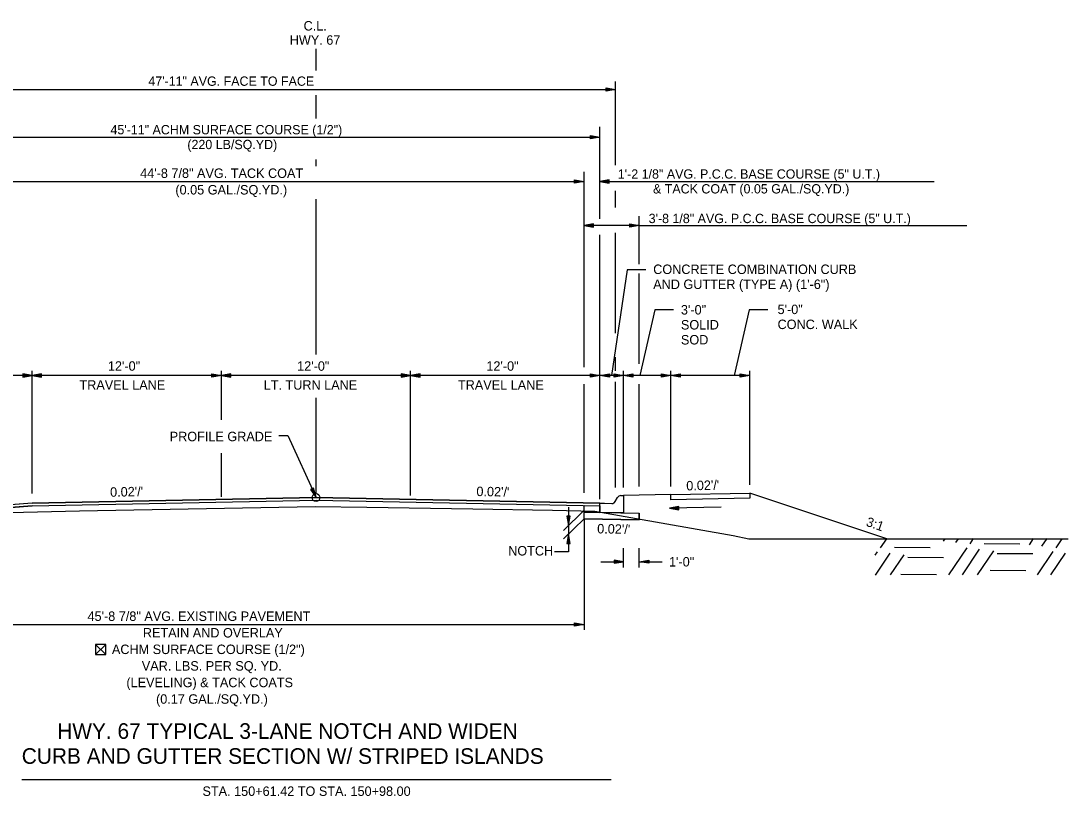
# Model space of a CAD drawing. Extents: x 1001270 to 1003428, y 1840152 to 1842912.
# Drawn here: x 1001595.7 to 1001662.1, y 1841962.8 to 1842011.9 of the extents above; entities that cross this region are included whole.
import ezdxf

# ---------------------------------------------------------------- set-up
doc = ezdxf.new("R2010")
doc.units = 0
for name, color, linetype in [('10', 7, 'Continuous'), ('19', 7, 'Continuous'), ('20', 7, 'Continuous'), ('8', 7, 'Continuous')]:
    doc.layers.add(name, color=color, linetype=linetype)

# ---------------------------------------------------------------- blocks, each defined once
blk = doc.blocks.new('TM')
at = {"layer": '8'}
for p, q in [((-120.309, 21.181), (-119.787, -20.829)), ((0, 0), (-120.309, 21.181)), ((-31.382, 2.945), (-120.176, 10.512)), ((-119.787, -20.829), (0, 0)), ((-119.911, -10.826), (-31.307, -3.057))]:
    blk.add_line(p, q, dxfattribs=at)

msp = doc.modelspace()

# ---------------------------------------------------------------- linework, layer by layer
at = {"layer": '10'}
for p, q in [((1001600.472, 1841972.41), (1001601.114, 1841971.769)), ((1001601.114, 1841972.41), (1001600.472, 1841971.769)), ((1001600.854, 1841971.769), (1001600.865, 1841971.769))]:
    msp.add_line(p, q, dxfattribs=at)
msp.add_lwpolyline([(1001600.865, 1841971.769), (1001601.114, 1841971.769), (1001601.114, 1841972.41), (1001600.472, 1841972.41), (1001600.472, 1841971.769), (1001600.854, 1841971.769)], dxfattribs=at)
at = {"layer": '19'}
for p, q in [((1001614.45, 1842008.782), (1001614.45, 1842010.174)), ((1001585.161, 1842007.592), (1001633.451, 1842007.592)), ((1001632.851, 1842007.487), (1001632.851, 1842007.697)), ((1001632.851, 1842007.697), (1001633.451, 1842007.592)), ((1001632.851, 1842007.642), (1001633.291, 1842007.607)), ((1001633.451, 1842007.592), (1001632.851, 1842007.487)), ((1001633.291, 1842007.577), (1001632.851, 1842007.537)), ((1001633.451, 1842002.779), (1001633.451, 1842008.094)), ((1001614.45, 1842005.749), (1001614.45, 1842007.222)), ((1001632.45, 1841999.391), (1001632.45, 1842005.216)), ((1001586.132, 1842004.564), (1001632.45, 1842004.564)), ((1001631.851, 1842004.459), (1001631.851, 1842004.669)), ((1001631.851, 1842004.669), (1001632.451, 1842004.564)), ((1001631.851, 1842004.614), (1001632.291, 1842004.579)), ((1001632.451, 1842004.564), (1001631.851, 1842004.459)), ((1001632.291, 1842004.549), (1001631.851, 1842004.509)), ((1001614.45, 1842002.732), (1001614.45, 1842003.158)), ((1001631.447, 1841989.976), (1001631.447, 1842002.356)), ((1001586.132, 1842001.756), (1001631.447, 1842001.756)), ((1001630.847, 1842001.651), (1001630.847, 1842001.861)), ((1001630.847, 1842001.861), (1001631.447, 1842001.756)), ((1001630.847, 1842001.806), (1001631.287, 1842001.771)), ((1001631.447, 1842001.756), (1001630.847, 1842001.651)), ((1001631.287, 1842001.741), (1001630.847, 1842001.701)), ((1001633.049, 1842001.861), (1001632.449, 1842001.756)), ((1001632.449, 1842001.756), (1001633.049, 1842001.651)), ((1001632.451, 1842001.756), (1001653.64, 1842001.756)), ((1001633.049, 1842001.806), (1001632.609, 1842001.771)), ((1001632.609, 1842001.741), (1001633.049, 1842001.701)), ((1001633.049, 1842001.651), (1001633.049, 1842001.861)), ((1001633.451, 1842000.11), (1001633.451, 1842001.153)), ((1001614.45, 1841990.776), (1001614.45, 1842000.637)), ((1001634.95, 1841996.51), (1001634.95, 1841999.556)), ((1001632.047, 1841999.061), (1001631.447, 1841998.956)), ((1001634.95, 1841998.956), (1001631.447, 1841998.956)), ((1001631.447, 1841998.956), (1001632.047, 1841998.851)), ((1001632.047, 1841999.006), (1001631.607, 1841998.971)), ((1001631.607, 1841998.941), (1001632.047, 1841998.901)), ((1001632.047, 1841998.851), (1001632.047, 1841999.061)), ((1001634.35, 1841998.851), (1001634.35, 1841999.061)), ((1001634.35, 1841999.061), (1001634.95, 1841998.956)), ((1001634.35, 1841999.006), (1001634.79, 1841998.971)), ((1001634.95, 1841998.956), (1001634.35, 1841998.851)), ((1001634.79, 1841998.941), (1001634.35, 1841998.901)), ((1001634.95, 1841998.956), (1001655.726, 1841998.956)), ((1001632.45, 1841981.606), (1001632.45, 1841998.367)), ((1001633.451, 1841992.137), (1001633.451, 1841998.498)), ((1001634.181, 1841996.147), (1001633.193, 1841989.455)), ((1001635.36, 1841996.147), (1001634.181, 1841996.147)), ((1001634.95, 1841990.196), (1001634.95, 1841995.93)), ((1001635.945, 1841993.612), (1001634.988, 1841989.455)), ((1001637.124, 1841993.612), (1001635.945, 1841993.612)), ((1001641.927, 1841993.612), (1001640.971, 1841989.455)), ((1001643.106, 1841993.612), (1001641.927, 1841993.612)), ((1001633.451, 1841989.747), (1001633.451, 1841990.615)), ((1001596.45, 1841981.966), (1001596.45, 1841989.755)), ((1001608.45, 1841986.642), (1001608.45, 1841989.755)), ((1001620.45, 1841981.846), (1001620.45, 1841989.755)), ((1001632.45, 1841981.606), (1001632.45, 1841989.755)), ((1001633.95, 1841982.356), (1001633.95, 1841989.755)), ((1001636.95, 1841982.416), (1001636.95, 1841989.755)), ((1001641.95, 1841982.516), (1001641.95, 1841989.755)), ((1001596.45, 1841989.455), (1001586.132, 1841989.455)), ((1001595.85, 1841989.56), (1001595.85, 1841989.35)), ((1001596.45, 1841989.455), (1001595.85, 1841989.56)), ((1001596.29, 1841989.47), (1001595.85, 1841989.505)), ((1001595.85, 1841989.35), (1001596.45, 1841989.455)), ((1001595.85, 1841989.4), (1001596.29, 1841989.44)), ((1001597.05, 1841989.56), (1001596.45, 1841989.455)), ((1001608.45, 1841989.455), (1001596.45, 1841989.455)), ((1001596.45, 1841989.455), (1001597.05, 1841989.35)), ((1001597.05, 1841989.505), (1001596.61, 1841989.47)), ((1001596.61, 1841989.44), (1001597.05, 1841989.4)), ((1001597.05, 1841989.35), (1001597.05, 1841989.56)), ((1001607.85, 1841989.35), (1001607.85, 1841989.56)), ((1001607.85, 1841989.56), (1001608.45, 1841989.455)), ((1001607.85, 1841989.505), (1001608.29, 1841989.47)), ((1001608.45, 1841989.455), (1001607.85, 1841989.35)), ((1001608.29, 1841989.44), (1001607.85, 1841989.4)), ((1001609.05, 1841989.56), (1001608.45, 1841989.455)), ((1001620.45, 1841989.455), (1001608.45, 1841989.455)), ((1001608.45, 1841989.455), (1001609.05, 1841989.35)), ((1001609.05, 1841989.505), (1001608.61, 1841989.47)), ((1001608.61, 1841989.44), (1001609.05, 1841989.4)), ((1001609.05, 1841989.35), (1001609.05, 1841989.56)), ((1001619.85, 1841989.56), (1001619.85, 1841989.35)), ((1001620.45, 1841989.455), (1001619.85, 1841989.56)), ((1001620.29, 1841989.47), (1001619.85, 1841989.505)), ((1001619.85, 1841989.35), (1001620.45, 1841989.455)), ((1001619.85, 1841989.4), (1001620.29, 1841989.44)), ((1001621.05, 1841989.56), (1001620.45, 1841989.455)), ((1001632.45, 1841989.455), (1001620.45, 1841989.455)), ((1001620.45, 1841989.455), (1001621.05, 1841989.35)), ((1001621.05, 1841989.505), (1001620.61, 1841989.47)), ((1001620.61, 1841989.44), (1001621.05, 1841989.4)), ((1001621.05, 1841989.35), (1001621.05, 1841989.56)), ((1001631.85, 1841989.35), (1001631.85, 1841989.56)), ((1001631.85, 1841989.56), (1001632.45, 1841989.455)), ((1001631.85, 1841989.505), (1001632.29, 1841989.47)), ((1001632.45, 1841989.455), (1001631.85, 1841989.35)), ((1001632.29, 1841989.44), (1001631.85, 1841989.4)), ((1001632.45, 1841989.455), (1001633.05, 1841989.56)), ((1001641.95, 1841989.455), (1001632.45, 1841989.455)), ((1001633.05, 1841989.35), (1001632.45, 1841989.455)), ((1001632.61, 1841989.47), (1001633.05, 1841989.505)), ((1001633.05, 1841989.4), (1001632.61, 1841989.44)), ((1001633.05, 1841989.56), (1001633.05, 1841989.35)), ((1001633.35, 1841989.35), (1001633.35, 1841989.56)), ((1001633.35, 1841989.56), (1001633.95, 1841989.455)), ((1001633.35, 1841989.505), (1001633.79, 1841989.47)), ((1001633.95, 1841989.455), (1001633.35, 1841989.35)), ((1001633.79, 1841989.44), (1001633.35, 1841989.4)), ((1001633.451, 1841982.347), (1001633.451, 1841989.062)), ((1001633.95, 1841989.455), (1001634.55, 1841989.56)), ((1001634.55, 1841989.35), (1001633.95, 1841989.455)), ((1001634.11, 1841989.47), (1001634.55, 1841989.505)), ((1001634.55, 1841989.4), (1001634.11, 1841989.44)), ((1001634.55, 1841989.56), (1001634.55, 1841989.35)), ((1001634.95, 1841982.417), (1001634.95, 1841988.911)), ((1001636.35, 1841989.35), (1001636.35, 1841989.56)), ((1001636.35, 1841989.56), (1001636.95, 1841989.455)), ((1001636.35, 1841989.505), (1001636.79, 1841989.47)), ((1001636.95, 1841989.455), (1001636.35, 1841989.35)), ((1001636.79, 1841989.44), (1001636.35, 1841989.4)), ((1001636.95, 1841989.455), (1001637.55, 1841989.56)), ((1001637.55, 1841989.35), (1001636.95, 1841989.455)), ((1001637.11, 1841989.47), (1001637.55, 1841989.505)), ((1001637.55, 1841989.4), (1001637.11, 1841989.44)), ((1001637.55, 1841989.56), (1001637.55, 1841989.35)), ((1001641.35, 1841989.35), (1001641.35, 1841989.56)), ((1001641.35, 1841989.56), (1001641.95, 1841989.455)), ((1001641.35, 1841989.505), (1001641.79, 1841989.47)), ((1001641.95, 1841989.455), (1001641.35, 1841989.35)), ((1001641.79, 1841989.44), (1001641.35, 1841989.4)), ((1001631.447, 1841982.025), (1001631.447, 1841988.895)), ((1001614.45, 1841981.966), (1001614.45, 1841988.039)), ((1001608.45, 1841981.766), (1001608.45, 1841984.521)), ((1001614.296, 1841982.305), (1001614.106, 1841982.218)), ((1001614.393, 1841981.865), (1001614.249, 1841982.279)), ((1001614.45, 1841981.716), (1001614.296, 1841982.305)), ((1001596.45, 1841981.356), (1001614.45, 1841981.716)), ((1001614.106, 1841982.218), (1001614.45, 1841981.716)), ((1001614.149, 1841982.234), (1001614.369, 1841981.856)), ((1001614.45, 1841981.716), (1001632.45, 1841981.356)), ((1001633.421, 1841981.466), (1001633.567, 1841981.717)), ((1001633.783, 1841981.841), (1001633.95, 1841981.841)), ((1001636.951, 1841981.902), (1001633.95, 1841981.841)), ((1001633.95, 1841981.841), (1001633.95, 1841981.508)), ((1001636.951, 1841981.902), (1001641.95, 1841982.001)), ((1001636.951, 1841981.568), (1001636.951, 1841981.902)), ((1001636.951, 1841981.902), (1001636.951, 1841981.902)), ((1001641.95, 1841981.668), (1001636.951, 1841981.568)), ((1001650.64, 1841979.104), (1001641.95, 1841982.001)), ((1001641.95, 1841982.001), (1001641.95, 1841981.668)), ((1001596.45, 1841981.356), (1001586.132, 1841980.557)), ((1001596.45, 1841981.19), (1001586.132, 1841980.391)), ((1001596.45, 1841981.19), (1001614.45, 1841981.55)), ((1001614.45, 1841981.55), (1001632.45, 1841981.19)), ((1001631.447, 1841980.376), (1001631.447, 1841981.21)), ((1001631.447, 1841981.21), (1001632.45, 1841981.19)), ((1001631.447, 1841980.793), (1001631.447, 1841981.21)), ((1001631.447, 1841981.21), (1001631.447, 1841981.21)), ((1001632.45, 1841981.356), (1001632.734, 1841981.351)), ((1001632.45, 1841981.19), (1001632.45, 1841980.773)), ((1001632.734, 1841981.351), (1001632.734, 1841981.35)), ((1001632.734, 1841981.35), (1001632.734, 1841981.351)), ((1001632.734, 1841981.351), (1001633.2, 1841981.341)), ((1001633.95, 1841981.508), (1001633.95, 1841981.326)), ((1001633.95, 1841981.326), (1001633.95, 1841980.746)), ((1001631.447, 1841980.907), (1001630.147, 1841979.634)), ((1001631.447, 1841980.376), (1001630.147, 1841979.104)), ((1001630.561, 1841980.538), (1001630.351, 1841980.538)), ((1001630.351, 1841980.538), (1001630.456, 1841979.938)), ((1001630.406, 1841980.538), (1001630.441, 1841980.098)), ((1001630.456, 1841979.938), (1001630.561, 1841980.538)), ((1001630.471, 1841980.098), (1001630.511, 1841980.538)), ((1001631.447, 1841980.793), (1001632.45, 1841980.773)), ((1001632.45, 1841980.773), (1001631.447, 1841980.793)), ((1001631.447, 1841980.793), (1001634.95, 1841980.726)), ((1001631.447, 1841980.376), (1001631.447, 1841980.793)), ((1001631.447, 1841980.793), (1001631.447, 1841980.793)), ((1001631.447, 1841980.376), (1001631.447, 1841973.323)), ((1001631.447, 1841980.376), (1001634.95, 1841980.306)), ((1001634.95, 1841980.306), (1001631.447, 1841980.376)), ((1001633.95, 1841980.746), (1001632.45, 1841980.776)), ((1001633.95, 1841980.746), (1001634.95, 1841980.726)), ((1001634.95, 1841980.306), (1001634.95, 1841980.726)), ((1001634.95, 1841980.726), (1001634.95, 1841980.306)), ((1001630.456, 1841979.407), (1001630.351, 1841978.807)), ((1001630.441, 1841979.247), (1001630.401, 1841978.807)), ((1001630.561, 1841978.807), (1001630.456, 1841979.407)), ((1001630.506, 1841978.807), (1001630.471, 1841979.247)), ((1001650.249, 1841978.521), (1001650.64, 1841979.104)), ((1001654.234, 1841978.956), (1001654.34, 1841979.106)), ((1001655.029, 1841978.864), (1001655.195, 1841979.108)), ((1001655.924, 1841978.772), (1001656.15, 1841979.11)), ((1001659.688, 1841978.716), (1001659.95, 1841979.111)), ((1001660.483, 1841978.624), (1001660.815, 1841979.113)), ((1001661.378, 1841978.532), (1001661.759, 1841979.106)), ((1001630.351, 1841978.807), (1001630.561, 1841978.807)), ((1001633.95, 1841977.273), (1001633.95, 1841978.511)), ((1001634.95, 1841977.273), (1001634.95, 1841978.511)), ((1001651.137, 1841978.561), (1001653.397, 1841978.539)), ((1001654.586, 1841976.808), (1001655.738, 1841978.53)), ((1001655.441, 1841976.811), (1001656.533, 1841978.438)), ((1001656.396, 1841976.813), (1001657.428, 1841978.346)), ((1001656.812, 1841978.801), (1001659.073, 1841978.79)), ((1001660.196, 1841976.814), (1001661.193, 1841978.29)), ((1001630.456, 1841978.279), (1001629.582, 1841978.279)), ((1001632.501, 1841977.651), (1001633.95, 1841977.651)), ((1001632.501, 1841977.651), (1001633.95, 1841977.651)), ((1001633.35, 1841977.756), (1001633.35, 1841977.546)), ((1001633.95, 1841977.651), (1001633.35, 1841977.756)), ((1001633.35, 1841977.756), (1001633.35, 1841977.546)), ((1001633.95, 1841977.651), (1001633.35, 1841977.756)), ((1001633.79, 1841977.666), (1001633.35, 1841977.701)), ((1001633.79, 1841977.666), (1001633.35, 1841977.701)), ((1001633.35, 1841977.546), (1001633.95, 1841977.651)), ((1001633.35, 1841977.546), (1001633.95, 1841977.651)), ((1001633.35, 1841977.596), (1001633.79, 1841977.636)), ((1001633.35, 1841977.596), (1001633.79, 1841977.636)), ((1001634.95, 1841977.651), (1001635.55, 1841977.756)), ((1001634.95, 1841977.651), (1001635.55, 1841977.756)), ((1001635.55, 1841977.546), (1001634.95, 1841977.651)), ((1001634.95, 1841977.651), (1001636.399, 1841977.651)), ((1001635.55, 1841977.546), (1001634.95, 1841977.651)), ((1001634.95, 1841977.651), (1001636.399, 1841977.651)), ((1001635.11, 1841977.666), (1001635.55, 1841977.701)), ((1001635.11, 1841977.666), (1001635.55, 1841977.701)), ((1001635.55, 1841977.596), (1001635.11, 1841977.636)), ((1001635.55, 1841977.596), (1001635.11, 1841977.636)), ((1001635.55, 1841977.756), (1001635.55, 1841977.546)), ((1001635.55, 1841977.756), (1001635.55, 1841977.546)), ((1001649.909, 1841978.054), (1001650.063, 1841978.279)), ((1001649.931, 1841976.805), (1001650.858, 1841978.187)), ((1001650.887, 1841976.807), (1001651.753, 1841978.095)), ((1001651.977, 1841977.931), (1001654.237, 1841977.91)), ((1001657.642, 1841978.173), (1001659.913, 1841978.16)), ((1001661.051, 1841976.817), (1001661.987, 1841978.198)), ((1001657.2, 1841977.102), (1001659.46, 1841977.081)), ((1001651.525, 1841976.852), (1001653.795, 1841976.84)), ((1001586.132, 1841973.671), (1001631.447, 1841973.671)), ((1001630.847, 1841973.566), (1001630.847, 1841973.776)), ((1001630.847, 1841973.776), (1001631.447, 1841973.671)), ((1001630.847, 1841973.721), (1001631.287, 1841973.686)), ((1001631.447, 1841973.671), (1001630.847, 1841973.566)), ((1001631.287, 1841973.656), (1001630.847, 1841973.616)), ((1001595.788, 1841963.844), (1001633.174, 1841963.844)), ((1001599.622, 1841963.844), (1001629.354, 1841963.844))]:
    msp.add_line(p, q, dxfattribs=at)
for points in [[(1001612.084, 1841985.649), (1001612.654, 1841985.649), (1001614.45, 1841981.716)], [(1001586.132, 1841980.557), (1001599.45, 1841980.878), (1001614.399, 1841981.148)], [(1001614.399, 1841981.148), (1001617.671, 1841981.096), (1001624.385, 1841981.003), (1001629.45, 1841980.916), (1001632.131, 1841980.855)], [(1001630.456, 1841981.104), (1001630.456, 1841978.279)], [(1001632.45, 1841980.776), (1001632.45, 1841980.94), (1001632.45, 1841981.19), (1001632.45, 1841981.356)], [(1001632.131, 1841980.855), (1001640.895, 1841979.301), (1001641.888, 1841979.105), (1001662.139, 1841979.103)]]:
    msp.add_lwpolyline(points, dxfattribs=at)
msp.add_lwpolyline([(1001614.45, 1841981.716), (1001596.45, 1841981.356), (1001586.132, 1841980.557), (1001586.132, 1841980.391), (1001596.45, 1841981.19), (1001614.45, 1841981.55), (1001632.45, 1841981.19), (1001632.45, 1841981.356)], close=True, dxfattribs=at)
msp.add_circle((1001614.45, 1841981.716), 0.25, dxfattribs=at)
for centre, start, end in [((1001633.783, 1841981.591), 90, 149.8381), ((1001633.205, 1841981.591), 268.85424, 329.83652)]:
    msp.add_arc(centre, 0.25, start, end, dxfattribs=at)
at = {"layer": '20'}
msp.add_line((1001640.131, 1841981.101), (1001636.861, 1841981.038), dxfattribs=at)

# ---------------------------------------------------------------- block references
at = {"layer": '19', "xscale": 0.0050063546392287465, "yscale": 0.005006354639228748, "rotation": -178.8817897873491}
msp.add_blockref('TM', (1001636.86, 1841981.04), dxfattribs=at)

# ---------------------------------------------------------------- texts
at = {"layer": '19'}
for s, height, p in [('C.L.', 0.6, (1001613.662, 1842011.323)), ('HWY. 67', 0.6, (1001612.783, 1842010.423)), ('47\'-11" AVG. FACE TO FACE', 0.59001, (1001603.817, 1842007.82)), ('45\'-11" ACHM SURFACE COURSE (1/2")', 0.59001, (1001601.416, 1842004.743)), ('(220 LB/SQ.YD)', 0.59001, (1001606.29, 1842003.803)), ('1\'-2 1/8" AVG. P.C.C. BASE COURSE (5" U.T.)', 0.59001, (1001633.589, 1842001.934)), ('& TACK COAT (0.05 GAL./SQ.YD.)', 0.59001, (1001635.819, 1842000.994)), ('3\'-8 1/8" AVG. P.C.C. BASE COURSE (5" U.T.)', 0.59001, (1001635.543, 1841999.115)), ('CONCRETE COMBINATION CURB', 0.6, (1001635.832, 1841995.888)), ('AND GUTTER (TYPE A) (1\'-6")', 0.6, (1001635.832, 1841994.938)), ('3\'-0"', 0.6, (1001637.59, 1841993.32)), ('5\'-0"', 0.6, (1001643.717, 1841993.347)), ('SOLID ', 0.6, (1001637.59, 1841992.37)), ('CONC. WALK', 0.6, (1001643.717, 1841992.397)), ('SOD', 0.6, (1001637.59, 1841991.42)), ('12\'-0"', 0.6, (1001601.252, 1841989.755)), ('12\'-0"', 0.6, (1001613.252, 1841989.755)), ('12\'-0"', 0.6, (1001625.252, 1841989.755)), ('TRAVEL LANE', 0.6, (1001599.45, 1841988.555)), ('LT. TURN LANE', 0.6, (1001611.133, 1841988.555)), ('TRAVEL LANE', 0.6, (1001623.45, 1841988.555)), ('PROFILE GRADE', 0.6, (1001605.171, 1841985.287)), ('NOTCH', 0.6, (1001626.636, 1841978.042))]:
    msp.add_text(s, height=height, dxfattribs=at).set_placement(p)
for s, height, rotation, p in [('44\'-8 7/8" AVG. TACK COAT', 0.6, 360, (1001603.298, 1842001.979)), ('(0.05 GAL./SQ.YD.)', 0.6, 360, (1001605.53, 1842000.929)), ("0.02'/'", 0.6, 1.14576, (1001601.398, 1841981.763)), ("0.02'/'", 0.6, 358.85424, (1001624.616, 1841981.812)), ("0.02'/'", 0.6, 1.42975, (1001637.936, 1841982.164)), ('3:1', 0.6, 340.49426, (1001649.283, 1841979.938)), ("0.02'/'", 0.6, 358.85424, (1001632.275, 1841979.446)), ('1\'-0"', 0.6, 360, (1001636.834, 1841977.344)), ('45\'-8 7/8" AVG. EXISTING PAVEMENT', 0.6, 360, (1001599.96, 1841973.894)), ('RETAIN AND OVERLAY', 0.6, 360, (1001603.468, 1841972.844)), ('ACHM SURFACE COURSE (1/2")', 0.6, 360, (1001601.507, 1841971.794)), ('VAR. LBS. PER SQ. YD.', 0.6, 360, (1001603.402, 1841970.744)), ('(LEVELING) & TACK COATS', 0.6, 360, (1001602.424, 1841969.694)), ('(0.17 GAL./SQ.YD.)', 0.6, 360, (1001604.304, 1841968.644)), ('HWY. 67 TYPICAL 3-LANE NOTCH AND WIDEN ', 0.98999, 359.99538, (1001598.037, 1841966.419)), ('CURB AND GUTTER SECTION W/ STRIPED ISLANDS', 0.98999, 359.99538, (1001595.788, 1841964.835)), ('STA. 150+61.42 TO STA. 150+98.00', 0.6, 359.99538, (1001607.249, 1841962.801))]:
    msp.add_text(s, height=height, rotation=rotation, dxfattribs=at).set_placement(p)

doc.saveas('drawing.dxf')
